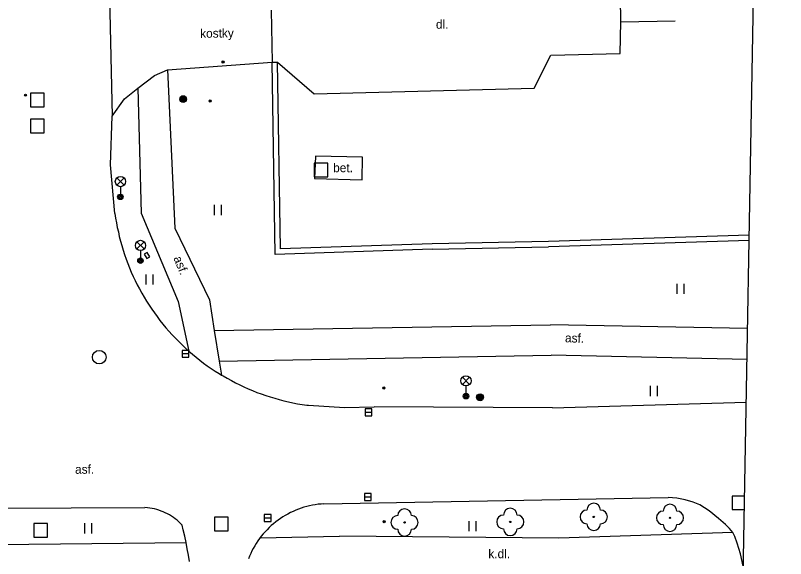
# Model space of a CAD drawing. Extents: x -641829 to -641525, y -1114855 to -1114359.
# Drawn here: x -641581.7 to -641525.3, y -1114535.8 to -1114496 of the extents above; entities that cross this region are included whole.
import ezdxf

# ---------------------------------------------------------------- set-up
doc = ezdxf.new("R2010")
doc.units = 0
for name, color, linetype in [('Vrstva 1', 7, 'Continuous'), ('Vrstva 10', 7, 'Continuous'), ('Vrstva 11', 7, 'Continuous'), ('Vrstva 20', 7, 'Continuous'), ('Vrstva 22', 7, 'Continuous'), ('Vrstva 24', 7, 'Continuous'), ('Vrstva 25', 7, 'Continuous'), ('Vrstva 26', 7, 'Continuous'), ('Vrstva 27', 7, 'Continuous'), ('Vrstva 33', 7, 'Continuous'), ('Vrstva 36', 7, 'Continuous'), ('Vrstva 40', 7, 'Continuous'), ('Vrstva 7', 7, 'Continuous'), ('Vrstva 8', 7, 'Continuous')]:
    doc.layers.add(name, color=color, linetype=linetype)

msp = doc.modelspace()

# ---------------------------------------------------------------- linework, layer by layer
at = {"layer": 'Vrstva 1'}
msp.add_line((-641533.66, -1114832.21), (-641525.3, -1114362.64), dxfattribs=at)
at = {"layer": 'Vrstva 10'}
for p, q in [((-641574.94, -1114489.73), (-641574.64, -1114503.41)), ((-641537.38, -1114496.49), (-641537.39, -1114493.5)), ((-641537.42, -1114498.8), (-641537.38, -1114496.49)), ((-641543.72, -1114501.36), (-641542.51, -1114498.93)), ((-641542.51, -1114498.93), (-641537.42, -1114498.8)), ((-641570.6, -1114500), (-641562.93, -1114499.44)), ((-641562.53, -1114499.43), (-641559.84, -1114501.77)), ((-641571.54, -1114500.43), (-641570.6, -1114500)), ((-641572.75, -1114501.34), (-641571.54, -1114500.43)), ((-641573.73, -1114502.14), (-641572.75, -1114501.34)), ((-641559.84, -1114501.77), (-641543.72, -1114501.36)), ((-641574.64, -1114503.41), (-641573.73, -1114502.14)), ((-641574.77, -1114506.96), (-641574.64, -1114503.41)), ((-641574.44, -1114510.54), (-641574.77, -1114506.96)), ((-641574.44, -1114510.54), (-641574.39, -1114510.88)), ((-641574.39, -1114510.88), (-641574.33, -1114511.22)), ((-641574.33, -1114511.22), (-641574.27, -1114511.56)), ((-641574.27, -1114511.56), (-641574.19, -1114511.89)), ((-641574.19, -1114511.89), (-641574.12, -1114512.23)), ((-641574.12, -1114512.23), (-641574.03, -1114512.56)), ((-641574.03, -1114512.56), (-641573.94, -1114512.89)), ((-641573.94, -1114512.89), (-641573.84, -1114513.22)), ((-641573.84, -1114513.22), (-641573.73, -1114513.55)), ((-641573.73, -1114513.55), (-641573.62, -1114513.88)), ((-641573.62, -1114513.88), (-641573.5, -1114514.2)), ((-641573.5, -1114514.2), (-641573.37, -1114514.52)), ((-641573.37, -1114514.52), (-641573.24, -1114514.84)), ((-641573.24, -1114514.84), (-641573.1, -1114515.15)), ((-641573.1, -1114515.15), (-641572.95, -1114515.46)), ((-641572.95, -1114515.46), (-641572.8, -1114515.77)), ((-641572.8, -1114515.77), (-641572.64, -1114516.07)), ((-641572.64, -1114516.07), (-641572.47, -1114516.38)), ((-641572.47, -1114516.38), (-641572.3, -1114516.67)), ((-641572.3, -1114516.67), (-641572.12, -1114516.97)), ((-641572.12, -1114516.97), (-641571.93, -1114517.26)), ((-641571.93, -1114517.26), (-641571.74, -1114517.54)), ((-641571.74, -1114517.54), (-641571.55, -1114517.83)), ((-641571.55, -1114517.83), (-641571.34, -1114518.1)), ((-641571.34, -1114518.1), (-641571.14, -1114518.38)), ((-641571.14, -1114518.38), (-641570.92, -1114518.65)), ((-641570.92, -1114518.65), (-641570.7, -1114518.91)), ((-641570.7, -1114518.91), (-641570.48, -1114519.17)), ((-641570.48, -1114519.17), (-641570.25, -1114519.43)), ((-641570.25, -1114519.43), (-641570.01, -1114519.68)), ((-641570.01, -1114519.68), (-641569.77, -1114519.93)), ((-641569.77, -1114519.93), (-641569.52, -1114520.17)), ((-641569.52, -1114520.17), (-641569.27, -1114520.4)), ((-641569.27, -1114520.4), (-641569.03, -1114520.62)), ((-641569.03, -1114520.62), (-641568.76, -1114520.86)), ((-641568.76, -1114520.86), (-641568.49, -1114521.08)), ((-641568.49, -1114521.08), (-641568.22, -1114521.29)), ((-641568.22, -1114521.29), (-641567.95, -1114521.5)), ((-641567.95, -1114521.5), (-641567.67, -1114521.7)), ((-641567.67, -1114521.7), (-641567.39, -1114521.9)), ((-641567.39, -1114521.9), (-641567.1, -1114522.09)), ((-641567.1, -1114522.09), (-641566.81, -1114522.27)), ((-641566.81, -1114522.27), (-641566.64, -1114522.38)), ((-641566.64, -1114522.38), (-641566.51, -1114522.45)), ((-641566.51, -1114522.45), (-641566.22, -1114522.62)), ((-641566.22, -1114522.62), (-641565.91, -1114522.79)), ((-641565.91, -1114522.79), (-641565.61, -1114522.95)), ((-641565.61, -1114522.95), (-641565.3, -1114523.1)), ((-641565.3, -1114523.1), (-641564.99, -1114523.25)), ((-641564.99, -1114523.25), (-641564.68, -1114523.39)), ((-641564.68, -1114523.39), (-641564.36, -1114523.52)), ((-641564.36, -1114523.52), (-641564.04, -1114523.65)), ((-641564.04, -1114523.65), (-641563.72, -1114523.76)), ((-641563.72, -1114523.76), (-641563.39, -1114523.88)), ((-641563.39, -1114523.88), (-641563.06, -1114523.98)), ((-641563.06, -1114523.98), (-641562.73, -1114524.08)), ((-641562.73, -1114524.08), (-641562.4, -1114524.18)), ((-641562.4, -1114524.18), (-641562.07, -1114524.26)), ((-641562.07, -1114524.26), (-641561.73, -1114524.34)), ((-641561.73, -1114524.34), (-641561.4, -1114524.41)), ((-641542.37, -1114524.79), (-641528.179, -1114524.362)), ((-641561.4, -1114524.41), (-641561.06, -1114524.48)), ((-641561.06, -1114524.48), (-641560.72, -1114524.53)), ((-641560.72, -1114524.53), (-641560.38, -1114524.58)), ((-641560.38, -1114524.58), (-641560.26, -1114524.6)), ((-641560.26, -1114524.6), (-641557.62, -1114524.76)), ((-641557.62, -1114524.76), (-641555.44, -1114524.72)), ((-641542.37, -1114524.79), (-641555.44, -1114524.72)), ((-641559.13, -1114531.82), (-641541.82, -1114531.51)), ((-641541.82, -1114531.51), (-641533.9, -1114531.35)), ((-641533.28, -1114531.4), (-641533.9, -1114531.35)), ((-641532.65, -1114531.53), (-641533.28, -1114531.4)), ((-641532.07, -1114531.7), (-641532.65, -1114531.53)), ((-641531.59, -1114531.89), (-641532.07, -1114531.7)), ((-641584.42, -1114532.15), (-641572.24, -1114532.1)), ((-641572.05, -1114532.12), (-641572.24, -1114532.1)), ((-641571.88, -1114532.14), (-641572.05, -1114532.12)), ((-641571.71, -1114532.17), (-641571.88, -1114532.14)), ((-641571.54, -1114532.2), (-641571.71, -1114532.17)), ((-641571.38, -1114532.24), (-641571.54, -1114532.2)), ((-641571.22, -1114532.29), (-641571.38, -1114532.24)), ((-641561, -1114532.21), (-641561.19, -1114532.29)), ((-641560.8, -1114532.14), (-641561, -1114532.21)), ((-641560.59, -1114532.08), (-641560.8, -1114532.14)), ((-641560.39, -1114532.02), (-641560.59, -1114532.08)), ((-641560.18, -1114531.97), (-641560.39, -1114532.02)), ((-641559.97, -1114531.93), (-641560.18, -1114531.97)), ((-641559.76, -1114531.89), (-641559.97, -1114531.93)), ((-641559.55, -1114531.86), (-641559.76, -1114531.89)), ((-641559.34, -1114531.84), (-641559.55, -1114531.86)), ((-641559.13, -1114531.82), (-641559.34, -1114531.84)), ((-641530.91, -1114532.33), (-641531.59, -1114531.89)), ((-641571.06, -1114532.35), (-641571.22, -1114532.29)), ((-641570.9, -1114532.41), (-641571.06, -1114532.35)), ((-641570.75, -1114532.48), (-641570.9, -1114532.41)), ((-641570.59, -1114532.56), (-641570.75, -1114532.48)), ((-641570.45, -1114532.64), (-641570.59, -1114532.56)), ((-641570.3, -1114532.73), (-641570.45, -1114532.64)), ((-641570.16, -1114532.82), (-641570.3, -1114532.73)), ((-641570.02, -1114532.92), (-641570.16, -1114532.82)), ((-641562.14, -1114532.78), (-641562.32, -1114532.9)), ((-641561.96, -1114532.67), (-641562.14, -1114532.78)), ((-641561.77, -1114532.57), (-641561.96, -1114532.67)), ((-641561.58, -1114532.47), (-641561.77, -1114532.57)), ((-641561.39, -1114532.38), (-641561.58, -1114532.47)), ((-641561.19, -1114532.29), (-641561.39, -1114532.38)), ((-641530.22, -1114532.9), (-641530.91, -1114532.33)), ((-641569.89, -1114533.03), (-641570.02, -1114532.92)), ((-641569.76, -1114533.14), (-641569.89, -1114533.03)), ((-641569.64, -1114533.26), (-641569.76, -1114533.14)), ((-641569.52, -1114533.38), (-641569.64, -1114533.26)), ((-641569.44, -1114533.74), (-641569.52, -1114533.38)), ((-641562.82, -1114533.28), (-641562.99, -1114533.42)), ((-641562.66, -1114533.15), (-641562.82, -1114533.28)), ((-641562.49, -1114533.02), (-641562.66, -1114533.15)), ((-641562.32, -1114532.9), (-641562.49, -1114533.02)), ((-641529.71, -1114533.35), (-641530.22, -1114532.9)), ((-641529.42, -1114533.63), (-641529.71, -1114533.35)), ((-641569.33, -1114534.2), (-641569.44, -1114533.74)), ((-641563.44, -1114533.87), (-641563.58, -1114534.03)), ((-641563.29, -1114533.72), (-641563.44, -1114533.87)), ((-641563.14, -1114533.57), (-641563.29, -1114533.72)), ((-641562.99, -1114533.42), (-641563.14, -1114533.57)), ((-641529.17, -1114533.92), (-641529.42, -1114533.63)), ((-641529.02, -1114534.23), (-641529.17, -1114533.92)), ((-641569.23, -1114534.66), (-641569.33, -1114534.2)), ((-641563.84, -1114534.37), (-641563.97, -1114534.54)), ((-641563.72, -1114534.2), (-641563.84, -1114534.37)), ((-641563.58, -1114534.03), (-641563.72, -1114534.2)), ((-641528.85, -1114534.7), (-641529.02, -1114534.23)), ((-641569.14, -1114535.13), (-641569.23, -1114534.66)), ((-641564.3, -1114535.09), (-641564.4, -1114535.27)), ((-641564.2, -1114534.9), (-641564.3, -1114535.09)), ((-641564.09, -1114534.72), (-641564.2, -1114534.9)), ((-641563.97, -1114534.54), (-641564.09, -1114534.72)), ((-641528.61, -1114535.48), (-641528.85, -1114534.7)), ((-641569.05, -1114535.59), (-641569.14, -1114535.13)), ((-641568.97, -1114536.06), (-641569.05, -1114535.59)), ((-641564.58, -1114535.66), (-641564.66, -1114535.86)), ((-641564.49, -1114535.47), (-641564.58, -1114535.66)), ((-641564.4, -1114535.27), (-641564.49, -1114535.47)), ((-641528.4, -1114536.39), (-641528.61, -1114535.48))]:
    msp.add_line(p, q, dxfattribs=at)
at = {"layer": 'Vrstva 11'}
for p, q in [((-641537.38, -1114496.49), (-641533.4, -1114496.41)), ((-641570.6, -1114500), (-641570.04, -1114511.62)), ((-641572.75, -1114501.34), (-641572.52, -1114510.52)), ((-641559.74, -1114506.33), (-641559.81, -1114507.98)), ((-641556.29, -1114506.41), (-641559.74, -1114506.33)), ((-641556.33, -1114508.06), (-641556.29, -1114506.41)), ((-641559.81, -1114507.98), (-641556.33, -1114508.06)), ((-641572.52, -1114510.52), (-641569.81, -1114516.99)), ((-641570.04, -1114511.62), (-641567.52, -1114516.86)), ((-641569.81, -1114516.99), (-641569.03, -1114520.62)), ((-641567.16, -1114519.12), (-641542.52, -1114518.71)), ((-641528.083, -1114518.963), (-641542.52, -1114518.71)), ((-641566.8, -1114521.36), (-641542.47, -1114520.92)), ((-641528.124, -1114521.24), (-641542.47, -1114520.92)), ((-641529.17, -1114533.92), (-641541.92, -1114534.34)), ((-641563.81, -1114534.32), (-641557.99, -1114534.2)), ((-641541.92, -1114534.34), (-641557.99, -1114534.2)), ((-641595.05, -1114534.95), (-641569.23, -1114534.66))]:
    msp.add_line(p, q, dxfattribs=at)
msp.add_lwpolyline([(-641567.52, -1114516.86), (-641567.16, -1114519.12), (-641566.8, -1114521.36), (-641566.64, -1114522.38)], dxfattribs=at)
at = {"layer": 'Vrstva 20'}
for centre, radius in [((-641566.52, -1114499.43), 0.075), ((-641566.52, -1114499.43), 0.0204), ((-641581, -1114501.86), 0.075), ((-641581, -1114501.86), 0.0204), ((-641567.47, -1114502.29), 0.075), ((-641567.47, -1114502.29), 0.0204), ((-641554.74, -1114523.33), 0.075), ((-641554.74, -1114523.33), 0.0204), ((-641554.72, -1114533.13), 0.075), ((-641554.72, -1114533.13), 0.0204)]:
    msp.add_circle(centre, radius, dxfattribs=at)
at = {"layer": 'Vrstva 22'}
for centre in [(-641539.36, -1114532.78), (-641533.77, -1114532.85), (-641553.22, -1114533.19), (-641545.47, -1114533.15)]:
    msp.add_circle(centre, 0.05, dxfattribs=at)
for centre, start, end in [((-641553.22, -1114532.69), 0, 180), ((-641545.47, -1114532.65), 0, 180), ((-641539.86, -1114532.78), 90, 270), ((-641539.36, -1114532.28), 0, 180), ((-641538.86, -1114532.78), 270, 90), ((-641533.77, -1114532.35), 0, 180), ((-641553.72, -1114533.19), 90, 270), ((-641552.72, -1114533.19), 270, 90), ((-641545.97, -1114533.15), 90, 270), ((-641544.97, -1114533.15), 270, 90), ((-641534.27, -1114532.85), 90, 270), ((-641533.27, -1114532.85), 270, 90), ((-641539.36, -1114533.28), 180, 0), ((-641533.77, -1114533.35), 180, 0), ((-641553.22, -1114533.69), 180, 0), ((-641545.47, -1114533.65), 180, 0)]:
    msp.add_arc(centre, 0.5, start, end, dxfattribs=at)
at = {"layer": 'Vrstva 24'}
msp.add_lwpolyline([(-641571.89, -1114513.72), (-641572.07, -1114513.39), (-641572.29, -1114513.51), (-641572.11, -1114513.84), (-641571.89, -1114513.72)], dxfattribs=at)
at = {"layer": 'Vrstva 25'}
for centre, radius in [((-641569.44, -1114502.15), 0.25), ((-641569.44, -1114502.15), 0.2), ((-641569.44, -1114502.15), 0.15), ((-641569.44, -1114502.15), 0.1), ((-641569.44, -1114502.15), 0.05), ((-641547.69, -1114524.01), 0.25), ((-641547.69, -1114524.01), 0.2), ((-641547.69, -1114524.01), 0.15), ((-641547.69, -1114524.01), 0.1), ((-641547.69, -1114524.01), 0.05)]:
    msp.add_circle(centre, radius, dxfattribs=at)
at = {"layer": 'Vrstva 26'}
for p, q in [((-641528.302, -1114531.25), (-641529.21, -1114531.25)), ((-641529.21, -1114531.25), (-641529.21, -1114532.25)), ((-641528.32, -1114532.25), (-641528.302, -1114531.25)), ((-641529.21, -1114532.25), (-641528.32, -1114532.25))]:
    msp.add_line(p, q, dxfattribs=at)
for points in [[(-641579.62, -1114501.71), (-641580.62, -1114501.71), (-641580.62, -1114502.71), (-641579.62, -1114502.71)], [(-641579.63, -1114503.62), (-641580.63, -1114503.62), (-641580.63, -1114504.62), (-641579.63, -1114504.62)], [(-641559.84, -1114507.84), (-641558.84, -1114507.84), (-641558.84, -1114506.84), (-641559.84, -1114506.84)], [(-641567.14, -1114533.81), (-641566.14, -1114533.81), (-641566.14, -1114532.81), (-641567.14, -1114532.81)], [(-641580.37, -1114534.26), (-641579.37, -1114534.26), (-641579.37, -1114533.26), (-641580.37, -1114533.26)]]:
    msp.add_lwpolyline(points, close=True, dxfattribs=at)
at = {"layer": 'Vrstva 27'}
for p, q in [((-641569.02, -1114520.82), (-641569.52, -1114520.82)), ((-641555.61, -1114525.12), (-641556.11, -1114525.12)), ((-641556.16, -1114531.32), (-641555.66, -1114531.32)), ((-641563.5, -1114532.86), (-641563, -1114532.86))]:
    msp.add_line(p, q, dxfattribs=at)
for points in [[(-641569.02, -1114520.57), (-641569.52, -1114520.57), (-641569.52, -1114521.07), (-641569.02, -1114521.07)], [(-641555.61, -1114524.87), (-641556.11, -1114524.87), (-641556.11, -1114525.37), (-641555.61, -1114525.37)], [(-641556.16, -1114531.57), (-641555.66, -1114531.57), (-641555.66, -1114531.07), (-641556.16, -1114531.07)], [(-641563.5, -1114533.11), (-641563, -1114533.11), (-641563, -1114532.61), (-641563.5, -1114532.61)]]:
    msp.add_lwpolyline(points, close=True, dxfattribs=at)
msp.add_circle((-641575.59, -1114521.07), 0.5, dxfattribs=at)
at = {"layer": 'Vrstva 33'}
for p, q in [((-641574.305, -1114508.46), (-641573.775, -1114507.93)), ((-641574.305, -1114507.93), (-641573.775, -1114508.46)), ((-641574.04, -1114508.57), (-641574.04, -1114509.32)), ((-641572.835, -1114513.14), (-641572.305, -1114512.61)), ((-641572.835, -1114512.61), (-641572.305, -1114513.14)), ((-641572.57, -1114513.25), (-641572.57, -1114514)), ((-641548.984, -1114523.07), (-641548.456, -1114522.54)), ((-641548.984, -1114522.54), (-641548.456, -1114523.07)), ((-641548.72, -1114523.18), (-641548.72, -1114523.93))]:
    msp.add_line(p, q, dxfattribs=at)
for centre, radius in [((-641574.04, -1114508.195), 0.375), ((-641574.04, -1114509.32), 0.2), ((-641574.04, -1114509.32), 0.145), ((-641574.04, -1114509.32), 0.0876), ((-641572.57, -1114512.875), 0.375), ((-641572.57, -1114514), 0.2), ((-641572.57, -1114514), 0.145), ((-641572.57, -1114514), 0.0876), ((-641548.72, -1114522.805), 0.375), ((-641548.72, -1114523.93), 0.2), ((-641548.72, -1114523.93), 0.145), ((-641548.72, -1114523.93), 0.0876)]:
    msp.add_circle(centre, radius, dxfattribs=at)
at = {"layer": 'Vrstva 36'}
for p, q in [((-641567.134, -1114510.652), (-641567.134, -1114509.904)), ((-641566.634, -1114510.652), (-641566.634, -1114509.904)), ((-641572.144, -1114515.754), (-641572.144, -1114515.002)), ((-641571.644, -1114515.754), (-641571.644, -1114515.002)), ((-641533.234, -1114516.434), (-641533.234, -1114515.682)), ((-641532.734, -1114516.434), (-641532.734, -1114515.682)), ((-641535.194, -1114523.922), (-641535.194, -1114523.174)), ((-641534.694, -1114523.922), (-641534.694, -1114523.174)), ((-641576.634, -1114533.994), (-641576.634, -1114533.242)), ((-641576.134, -1114533.994), (-641576.134, -1114533.242)), ((-641548.474, -1114533.832), (-641548.474, -1114533.084)), ((-641547.974, -1114533.832), (-641547.974, -1114533.084))]:
    msp.add_line(p, q, dxfattribs=at)
at = {"layer": 'Vrstva 7'}
for p, q in [((-641562.93, -1114499.44), (-641562.53, -1114499.43)), ((-641562.71, -1114513.54), (-641562.93, -1114499.44)), ((-641562.32, -1114513.13), (-641562.53, -1114499.43)), ((-641527.961, -1114512.118), (-641542.67, -1114512.59)), ((-641527.968, -1114512.519), (-641542.66, -1114512.99)), ((-641551.2, -1114512.76), (-641562.32, -1114513.13)), ((-641542.67, -1114512.59), (-641551.2, -1114512.76)), ((-641551.19, -1114513.16), (-641542.66, -1114512.99)), ((-641551.19, -1114513.16), (-641562.71, -1114513.54))]:
    msp.add_line(p, q, dxfattribs=at)
at = {"layer": 'Vrstva 8'}
msp.add_line((-641562.99, -1114495.64), (-641562.93, -1114499.44), dxfattribs=at)

# ---------------------------------------------------------------- texts
at = {"layer": 'Vrstva 40'}
for s, p in [('dl.', (-641550.92, -1114496.99)), ('bet.', (-641558.45, -1114507.51)), ('k.dl.', (-641547.08, -1114535.81))]:
    msp.add_text(s, height=0.65, dxfattribs=at).set_placement(p)
for s, height, rotation, p in [('kostky', 0.6499, 0.7944, (-641568.19, -1114497.66)), ('asf.', 0.6499, 292.7267, (-641570.17, -1114513.81)), ('asf.', 0.6499, 358.7212, (-641541.47, -1114519.98)), ('asf.', 0.65, 0.2353, (-641577.36, -1114529.62))]:
    msp.add_text(s, height=height, rotation=rotation, dxfattribs=at).set_placement(p)

doc.saveas('drawing.dxf')
